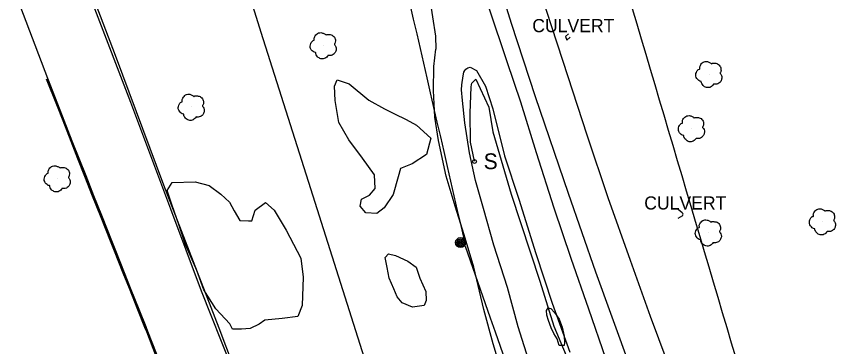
# Model space of a CAD drawing. Extents: x 368532 to 392481, y 10654822 to 10676899.
# Drawn here: x 375749.1 to 376060.4, y 10665955.9 to 10666081.5 of the extents above; entities that cross this region are included whole.
import ezdxf

# ---------------------------------------------------------------- set-up
doc = ezdxf.new("R2010")
doc.units = 0
for name, color, linetype in [('p_Catenary', 7, 'Continuous'), ('p_drainage culvert', 7, 'Continuous'), ('p_railroad rr control', 7, 'Continuous'), ('p_road - paved curb', 7, 'Continuous'), ('p_road dirt road', 7, 'Continuous'), ('p_structure fence', 7, 'Continuous'), ('p_structure sign', 7, 'Continuous'), ('p_utility general pole', 7, 'Continuous'), ('p_veg tree', 7, 'Continuous'), ('p_veg woods', 7, 'Continuous')]:
    doc.layers.add(name, color=color, linetype=linetype)

msp = doc.modelspace()

# ---------------------------------------------------------------- linework, layer by layer
at = {"layer": 'p_Catenary'}
for points in [[(375898.63, 10666086.06), (375899.92, 10666080.46), (375901.21, 10666074.86), (375902.49, 10666069.25), (375903.78, 10666063.65), (375905.07, 10666058.05), (375906.36, 10666052.45), (375907.64, 10666046.84), (375908.93, 10666041.24), (375910.22, 10666035.64), (375911.5, 10666030.03), (375912.79, 10666024.43), (375914.08, 10666018.83), (375915.37, 10666013.23), (375916.65, 10666007.62), (375917.94, 10666002.02), (375919.23, 10665996.42)], [(375983.15, 10666084.44), (375984.86, 10666078.67), (375986.57, 10666072.89), (375988.28, 10666067.12), (375989.99, 10666061.34), (375991.69, 10666055.56), (375993.4, 10666049.79), (375995.11, 10666044.01), (375996.82, 10666038.24), (375998.53, 10666032.46), (376000.24, 10666026.69), (376001.94, 10666020.91), (376003.65, 10666015.14), (376005.36, 10666009.36), (376007.07, 10666003.58), (376008.78, 10665997.81), (376010.49, 10665992.03), (376012.19, 10665986.26), (376013.9, 10665980.48), (376015.61, 10665974.71), (376017.32, 10665968.93), (376019.03, 10665963.16), (376020.74, 10665957.38), (376022.45, 10665951.6)], [(375919.69, 10665994.07), (375921.59, 10665988.63), (375923.48, 10665983.2), (375925.38, 10665977.77), (375927.27, 10665972.33), (375929.17, 10665966.9), (375931.06, 10665961.47), (375932.96, 10665956.04), (375934.85, 10665950.6)]]:
    msp.add_lwpolyline(points, dxfattribs=at)
at = {"layer": 'p_drainage culvert'}
for p, q in [((375958.88, 10666074.82), (375957.71, 10666073.83)), ((375957.71, 10666073.83), (375958.31, 10666072.47)), ((375958.31, 10666072.47), (375959.6, 10666073.53)), ((376002.1, 10666006.82), (376000.56, 10666008.09)), ((376000.64, 10666004.7), (376002.35, 10666005.81)), ((376002.33, 10666006.55), (376002.1, 10666006.82)), ((376002.45, 10666006.25), (376002.33, 10666006.55)), ((376002.35, 10666005.81), (376002.41, 10666005.96)), ((376002.41, 10666005.96), (376002.45, 10666006.25))]:
    msp.add_line(p, q, dxfattribs=at)
at = {"layer": 'p_railroad rr control'}
for points in [[(376032.08, 10665860.05), (376019.89, 10665889.9), (376008.13, 10665919.26), (375999.2, 10665942.84), (375990.13, 10665967.39), (375982.47, 10665988.67), (375974.03, 10666012.45), (375965.98, 10666036.31), (375958.74, 10666058.44), (375950.52, 10666083.7), (375941.44, 10666113.47), (375933.11, 10666141.34), (375926.18, 10666165.26), (375922.44, 10666177.51)], [(375810.5, 10666175.02), (375825.34, 10666128.75), (375842.01, 10666075.41), (375860.86, 10666016.02), (375879.57, 10665956.9), (375893.91, 10665911.69), (375912.71, 10665852.51)], [(375909.42, 10666171.59), (375918.72, 10666139.81), (375928.11, 10666107.91), (375937.15, 10666078.94), (375946.3, 10666051.05), (375958.77, 10666014.3), (375969.16, 10665984.31), (375982.15, 10665948.74), (375997.05, 10665910.08), (376009.94, 10665877.46), (376018.74, 10665855.38)]]:
    msp.add_lwpolyline(points, dxfattribs=at)
at = {"layer": 'p_road - paved curb'}
for p, q in [((375749.09, 10666089.26), (375760.92, 10666057.94)), ((375792.54, 10666048.75), (375778.92, 10666084.39)), ((375760.45, 10666057.76), (375764.28, 10666048)), ((375760.78, 10666057.89), (375764.61, 10666048.13)), ((375760.92, 10666057.94), (375764.75, 10666048.18)), ((375764.28, 10666048), (375766.69, 10666041.85)), ((375764.61, 10666048.13), (375767.02, 10666041.98)), ((375764.75, 10666048.18), (375767.16, 10666042.03)), ((375807.74, 10666008.19), (375792.54, 10666048.75)), ((375766.69, 10666041.85), (375769.75, 10666033.97)), ((375767.02, 10666041.98), (375770.08, 10666034.1)), ((375767.16, 10666042.03), (375770.22, 10666034.15)), ((375769.75, 10666033.97), (375772.34, 10666027.39)), ((375770.08, 10666034.1), (375772.67, 10666027.52)), ((375770.22, 10666034.15), (375772.81, 10666027.57)), ((375772.67, 10666027.52), (375775.29, 10666020.88)), ((375772.81, 10666027.57), (375775.43, 10666020.93)), ((375772.34, 10666027.39), (375774.96, 10666020.75)), ((375774.96, 10666020.75), (375777.93, 10666013.22)), ((375775.29, 10666020.88), (375778.25, 10666013.34)), ((375775.43, 10666020.93), (375778.39, 10666013.4)), ((375777.93, 10666013.22), (375780.92, 10666005.7)), ((375778.25, 10666013.34), (375781.24, 10666005.82)), ((375778.39, 10666013.4), (375781.38, 10666005.88)), ((375781.24, 10666005.82), (375785.32, 10665995.57)), ((375781.38, 10666005.88), (375785.46, 10665995.63)), ((375819.49, 10665976.98), (375807.74, 10666008.19)), ((375780.92, 10666005.7), (375785, 10665995.45)), ((375785, 10665995.45), (375786.25, 10665992.3)), ((375785.32, 10665995.57), (375786.57, 10665992.43)), ((375785.46, 10665995.63), (375786.71, 10665992.49)), ((375786.25, 10665992.3), (375789.59, 10665983.94)), ((375786.57, 10665992.43), (375789.91, 10665984.06)), ((375786.71, 10665992.49), (375790.05, 10665984.12)), ((375789.59, 10665983.94), (375791.89, 10665978.1)), ((375789.91, 10665984.06), (375792.21, 10665978.23)), ((375790.05, 10665984.12), (375792.35, 10665978.29)), ((375791.89, 10665978.1), (375795.17, 10665969.96)), ((375792.21, 10665978.23), (375795.49, 10665970.09)), ((375792.35, 10665978.29), (375795.63, 10665970.15)), ((375832.07, 10665945.21), (375819.49, 10665976.98)), ((375795.17, 10665969.96), (375797.78, 10665963.32)), ((375795.49, 10665970.09), (375798.11, 10665963.45)), ((375795.63, 10665970.15), (375798.25, 10665963.5)), ((375797.78, 10665963.32), (375798.48, 10665961.62)), ((375798.11, 10665963.45), (375798.81, 10665961.75)), ((375798.25, 10665963.5), (375798.95, 10665961.8)), ((375798.48, 10665961.62), (375803.4, 10665949.04)), ((375798.81, 10665961.75), (375803.73, 10665949.17)), ((375798.95, 10665961.8), (375803.87, 10665949.22))]:
    msp.add_line(p, q, dxfattribs=at)
at = {"layer": 'p_road dirt road'}
for p, q in [((375905.99, 10666089.73), (375908.37, 10666073.89)), ((375935.6, 10666064.24), (375928.7, 10666084.55)), ((375908.37, 10666073.89), (375908.49, 10666069.05)), ((375907.7, 10666062.39), (375908.49, 10666069.05)), ((375907.61, 10666053.29), (375907.7, 10666062.39)), ((375919.89, 10666061.41), (375920.68, 10666061.94)), ((375920.68, 10666061.94), (375921.58, 10666062.19)), ((375921.58, 10666062.19), (375923.99, 10666060.86)), ((375940.82, 10666048.88), (375935.6, 10666064.24)), ((375918.4, 10666055.45), (375918.84, 10666058.91)), ((375918.84, 10666058.91), (375919.18, 10666060.2)), ((375919.18, 10666060.2), (375919.54, 10666060.92)), ((375919.54, 10666060.92), (375919.89, 10666061.41)), ((375923.99, 10666060.86), (375927.33, 10666054.88)), ((375908.14, 10666043.11), (375907.61, 10666053.29)), ((375918.24, 10666053.57), (375918.4, 10666055.45)), ((375918.61, 10666049.54), (375918.24, 10666053.57)), ((375927.33, 10666054.88), (375930.17, 10666046.35)), ((375919.52, 10666041.02), (375918.61, 10666049.54)), ((375930.17, 10666046.35), (375934.63, 10666028.48)), ((375946.73, 10666029.54), (375940.82, 10666048.88)), ((375909.51, 10666034.21), (375908.14, 10666043.11)), ((375921.25, 10666029.58), (375919.52, 10666041.02)), ((375912.45, 10666020.71), (375909.51, 10666034.21)), ((375923.56, 10666019.03), (375921.25, 10666029.58)), ((375934.63, 10666028.48), (375940.04, 10666011.93)), ((375953.47, 10666008.59), (375946.73, 10666029.54)), ((375915.88, 10666009.37), (375912.45, 10666020.71)), ((375926.66, 10666008.46), (375923.56, 10666019.03)), ((375940.04, 10666011.93), (375946.48, 10665991.27)), ((375919.31, 10665998.47), (375915.88, 10666009.37)), ((375930.51, 10665994.42), (375926.66, 10666008.46)), ((375959.91, 10665989.4), (375953.47, 10666008.59)), ((375922.99, 10665986.1), (375919.31, 10665998.47)), ((375935.67, 10665978.39), (375930.51, 10665994.42)), ((375946.48, 10665991.27), (375952.72, 10665972.37)), ((375966.6, 10665970.17), (375959.91, 10665989.4)), ((375926.75, 10665970.02), (375922.99, 10665986.1)), ((375939.81, 10665963.48), (375935.67, 10665978.39)), ((375952.72, 10665972.37), (375959.42, 10665953.85)), ((375930.22, 10665956.94), (375926.75, 10665970.02)), ((375973.1, 10665951.43), (375966.6, 10665970.17)), ((375945, 10665946.9), (375939.81, 10665963.48)), ((375934.95, 10665941.66), (375930.22, 10665956.94))]:
    msp.add_line(p, q, dxfattribs=at)
at = {"layer": 'p_structure fence'}
for p, q in [((375769.89, 10666110.87), (375786.65, 10666066.67)), ((375786.65, 10666066.67), (375804.98, 10666017.37)), ((375921.92, 10666054.59), (375922.02, 10666055.56)), ((375922.02, 10666055.56), (375922.14, 10666056.09)), ((375922.14, 10666056.09), (375923.65, 10666057.59)), ((375923.65, 10666057.59), (375928.63, 10666046.9)), ((375921.48, 10666044.82), (375921.92, 10666054.59)), ((375928.63, 10666046.9), (375930.1, 10666037.51)), ((375921.64, 10666033.61), (375921.48, 10666044.82)), ((375930.1, 10666037.51), (375937.1, 10666013.9)), ((375923.17, 10666026.43), (375921.64, 10666033.61)), ((375804.98, 10666017.37), (375825.99, 10665962.99)), ((375937.1, 10666013.9), (375947.97, 10665980.84)), ((375947.97, 10665980.84), (375953.39, 10665963.73)), ((375825.99, 10665962.99), (375846.86, 10665908.84)), ((375953.39, 10665963.73), (375968.82, 10665926.6))]:
    msp.add_line(p, q, dxfattribs=at)
at = {"layer": 'p_structure sign'}
msp.add_circle((375923.19, 10666026.28), 0.713, dxfattribs=at)
at = {"layer": 'p_utility general pole'}
for radius in [1.9, 1.44, 0.973, 0.539, 0.192]:
    msp.add_circle((375917.9, 10665995.48), radius, dxfattribs=at)
at = {"layer": 'p_veg tree'}
for p, q in [((375865.87, 10666070.43), (375865.87, 10666070.43)), ((376012.41, 10666059.5), (376012.41, 10666059.5)), ((375815.72, 10666047.05), (375815.72, 10666047.05)), ((376005.8, 10666038.89), (376005.8, 10666038.89)), ((375764.79, 10666019.86), (375764.79, 10666019.86)), ((376055.59, 10666003.49), (376055.59, 10666003.49)), ((376012.22, 10665999.26), (376012.22, 10665999.26))]:
    msp.add_line(p, q, dxfattribs=at)
for points in [[(375867.52, 10666066.61), (375866.4, 10666065.54), (375864.79, 10666065.35), (375863.51, 10666066.14), (375863.01, 10666066.83), (375862.83, 10666067.51), (375862.83, 10666067.66), (375862.72, 10666067.69), (375861.84, 10666068.06), (375860.77, 10666069.67), (375861.17, 10666071.54), (375862.17, 10666072.38), (375862.3, 10666072.44), (375862.29, 10666072.56), (375862.48, 10666073.77), (375863.55, 10666074.97), (375865.21, 10666075.22), (375866.21, 10666074.78), (375866.63, 10666074.43), (375866.7, 10666074.34), (375866.77, 10666074.41), (375867.41, 10666074.61), (375868.69, 10666074.49), (375869.93, 10666073.53), (375870.33, 10666072.19), (375870.07, 10666071.09), (375869.93, 10666070.86), (375869.92, 10666070.79), (375869.96, 10666070.74), (375870.23, 10666070.38), (375870.63, 10666069.48), (375870.48, 10666068.28), (375869.83, 10666067.2), (375868.36, 10666066.56), (375867.5, 10666066.6)], [(376014.06, 10666055.68), (376012.93, 10666054.61), (376011.33, 10666054.42), (376010.05, 10666055.21), (376009.54, 10666055.9), (376009.37, 10666056.58), (376009.37, 10666056.73), (376009.26, 10666056.75), (376008.38, 10666057.13), (376007.31, 10666058.74), (376007.71, 10666060.61), (376008.7, 10666061.45), (376008.84, 10666061.51), (376008.82, 10666061.63), (376009.02, 10666062.83), (376010.09, 10666064.04), (376011.75, 10666064.28), (376012.74, 10666063.85), (376013.17, 10666063.5), (376013.23, 10666063.4), (376013.31, 10666063.48), (376013.95, 10666063.68), (376015.22, 10666063.56), (376016.46, 10666062.59), (376016.86, 10666061.26), (376016.61, 10666060.15), (376016.46, 10666059.93), (376016.46, 10666059.86), (376016.5, 10666059.81), (376016.77, 10666059.44), (376017.16, 10666058.55), (376017.02, 10666057.35), (376016.36, 10666056.27), (376014.9, 10666055.63), (376014.04, 10666055.67)], [(375817.37, 10666043.23), (375816.24, 10666042.16), (375814.64, 10666041.97), (375813.36, 10666042.76), (375812.85, 10666043.45), (375812.68, 10666044.13), (375812.68, 10666044.28), (375812.57, 10666044.3), (375811.69, 10666044.68), (375810.62, 10666046.29), (375811.02, 10666048.16), (375812.01, 10666049), (375812.15, 10666049.06), (375812.13, 10666049.18), (375812.33, 10666050.38), (375813.4, 10666051.59), (375815.06, 10666051.83), (375816.05, 10666051.4), (375816.48, 10666051.05), (375816.54, 10666050.95), (375816.62, 10666051.03), (375817.26, 10666051.23), (375818.53, 10666051.11), (375819.77, 10666050.14), (375820.18, 10666048.81), (375819.92, 10666047.7), (375819.78, 10666047.48), (375819.77, 10666047.41), (375819.81, 10666047.36), (375820.08, 10666046.99), (375820.47, 10666046.1), (375820.33, 10666044.9), (375819.67, 10666043.82), (375818.21, 10666043.18), (375817.35, 10666043.22)], [(376007.45, 10666035.07), (376006.33, 10666034), (376004.72, 10666033.81), (376003.44, 10666034.6), (376002.94, 10666035.29), (376002.76, 10666035.97), (376002.76, 10666036.12), (376002.65, 10666036.14), (376001.77, 10666036.52), (376000.7, 10666038.13), (376001.1, 10666040), (376002.1, 10666040.84), (376002.23, 10666040.9), (376002.22, 10666041.02), (376002.41, 10666042.23), (376003.49, 10666043.43), (376005.14, 10666043.67), (376006.14, 10666043.24), (376006.56, 10666042.89), (376006.63, 10666042.8), (376006.7, 10666042.87), (376007.34, 10666043.07), (376008.62, 10666042.95), (376009.86, 10666041.99), (376010.26, 10666040.65), (376010, 10666039.55), (376009.86, 10666039.32), (376009.86, 10666039.25), (376009.89, 10666039.2), (376010.16, 10666038.84), (376010.56, 10666037.94), (376010.41, 10666036.74), (376009.76, 10666035.66), (376008.29, 10666035.02), (376007.43, 10666035.06)], [(375766.44, 10666016.04), (375765.32, 10666014.97), (375763.71, 10666014.78), (375762.43, 10666015.57), (375761.93, 10666016.26), (375761.75, 10666016.94), (375761.75, 10666017.09), (375761.64, 10666017.11), (375760.76, 10666017.49), (375759.69, 10666019.1), (375760.09, 10666020.97), (375761.09, 10666021.81), (375761.22, 10666021.87), (375761.21, 10666021.99), (375761.4, 10666023.19), (375762.47, 10666024.4), (375764.13, 10666024.64), (375765.13, 10666024.21), (375765.55, 10666023.86), (375765.62, 10666023.76), (375765.69, 10666023.84), (375766.33, 10666024.04), (375767.61, 10666023.92), (375768.85, 10666022.95), (375769.25, 10666021.62), (375768.99, 10666020.51), (375768.85, 10666020.29), (375768.84, 10666020.22), (375768.88, 10666020.17), (375769.15, 10666019.8), (375769.55, 10666018.91), (375769.4, 10666017.71), (375768.75, 10666016.63), (375767.28, 10666015.99), (375766.42, 10666016.03)], [(376057.24, 10665999.67), (376056.11, 10665998.6), (376054.51, 10665998.41), (376053.23, 10665999.2), (376052.72, 10665999.89), (376052.55, 10666000.57), (376052.55, 10666000.72), (376052.44, 10666000.74), (376051.56, 10666001.12), (376050.49, 10666002.73), (376050.89, 10666004.6), (376051.88, 10666005.44), (376052.02, 10666005.5), (376052, 10666005.62), (376052.2, 10666006.83), (376053.27, 10666008.03), (376054.92, 10666008.28), (376055.92, 10666007.84), (376056.35, 10666007.49), (376056.41, 10666007.4), (376056.48, 10666007.47), (376057.13, 10666007.67), (376058.4, 10666007.55), (376059.64, 10666006.59), (376060.04, 10666005.25), (376059.79, 10666004.15), (376059.64, 10666003.92), (376059.64, 10666003.85), (376059.68, 10666003.8), (376059.95, 10666003.44), (376060.34, 10666002.54), (376060.2, 10666001.34), (376059.54, 10666000.26), (376058.08, 10665999.62), (376057.22, 10665999.66)], [(376013.87, 10665995.44), (376012.74, 10665994.36), (376011.14, 10665994.18), (376009.86, 10665994.97), (376009.36, 10665995.65), (376009.18, 10665996.33), (376009.18, 10665996.48), (376009.07, 10665996.51), (376008.19, 10665996.89), (376007.12, 10665998.49), (376007.52, 10666000.37), (376008.52, 10666001.21), (376008.65, 10666001.27), (376008.63, 10666001.39), (376008.83, 10666002.59), (376009.9, 10666003.8), (376011.56, 10666004.04), (376012.56, 10666003.61), (376012.98, 10666003.25), (376013.04, 10666003.16), (376013.12, 10666003.24), (376013.76, 10666003.43), (376015.03, 10666003.32), (376016.28, 10666002.35), (376016.68, 10666001.02), (376016.42, 10665999.91), (376016.28, 10665999.69), (376016.27, 10665999.62), (376016.31, 10665999.57), (376016.58, 10665999.2), (376016.98, 10665998.31), (376016.83, 10665997.1), (376016.17, 10665996.03), (376014.71, 10665995.38), (376013.85, 10665995.43)]]:
    msp.add_spline(points, degree=3, dxfattribs=at)
at = {"layer": 'p_veg woods'}
for points in [[(375875.49, 10666055.81), (375883.07, 10666049.57), (375888.97, 10666046.26), (375892.83, 10666044.39), (375897.23, 10666042.2), (375901.13, 10666040.16), (375906.64, 10666035.17), (375904.96, 10666029.01), (375899.52, 10666025.37), (375895.03, 10666023.58), (375894.16, 10666020.4), (375892.26, 10666013.77), (375888.9, 10666008.63), (375886.08, 10666006.54), (375881.86, 10666006.74), (375879.72, 10666009.35), (375880.27, 10666012.01), (375883.3, 10666013.51), (375885.48, 10666016.01), (375885.17, 10666021.17), (375880.59, 10666027.56), (375875.4, 10666034.47), (375871.6, 10666041.1), (375870.29, 10666049.53), (375870.01, 10666054.93), (375870.96, 10666057.29)], [(375830.24, 10665964.61), (375824.94, 10665970.3), (375820.38, 10665977.52), (375817.62, 10665984.84), (375813.3, 10665994.79), (375810.99, 10666001.99), (375808.12, 10666009.88), (375806.39, 10666015.32), (375808.34, 10666018.35), (375817.03, 10666018.53), (375822.35, 10666017.15), (375826.77, 10666013.83), (375830.03, 10666010.86), (375831.86, 10666007.54), (375834.05, 10666003.92), (375837.31, 10666003.75), (375838.55, 10666003.74), (375839.86, 10666007.75), (375843.74, 10666010.71), (375847.04, 10666007.78), (375851.65, 10666000.15), (375857.17, 10665989.6), (375858.04, 10665982.26), (375857.67, 10665971.6), (375856.03, 10665967.31), (375850.13, 10665966.55), (375843.46, 10665965.99), (375841.33, 10665964.47), (375837.9, 10665962.77), (375834.67, 10665962.49), (375831.25, 10665962.59)], [(375899.61, 10665970.97), (375895.7, 10665972.59), (375893.8, 10665974.8), (375892.53, 10665977.94), (375890.77, 10665981.91), (375889.97, 10665986), (375889.19, 10665989.75), (375890.49, 10665991.16), (375893.18, 10665990.51), (375897.8, 10665988.45), (375901.02, 10665986.17), (375902.38, 10665981.97), (375904.64, 10665976.92), (375904.76, 10665973.44), (375904.1, 10665971.51)], [(375955.31, 10665956.34), (375954.62, 10665958.86), (375953.33, 10665960.95), (375952.35, 10665963.04), (375951.28, 10665965.8), (375950.66, 10665967.92), (375950.52, 10665969.6), (375951.24, 10665970.61), (375952.22, 10665970.46), (375953.63, 10665968.85), (375955.3, 10665966.37), (375956.48, 10665963.31), (375957.28, 10665959.82), (375957.41, 10665957.37), (375957.3, 10665956.39)]]:
    msp.add_lwpolyline(points, close=True, dxfattribs=at)

# ---------------------------------------------------------------- texts
at = {"layer": 'p_drainage culvert'}
for p in [(375943.28, 10666075.45), (375985.83, 10666008.03)]:
    msp.add_text(' CULVERT', height=5, dxfattribs=at).set_placement(p)
at = {"layer": 'p_structure sign'}
msp.add_text('S', height=6, dxfattribs=at).set_placement((375926.65, 10666023.38))

doc.saveas('drawing.dxf')
